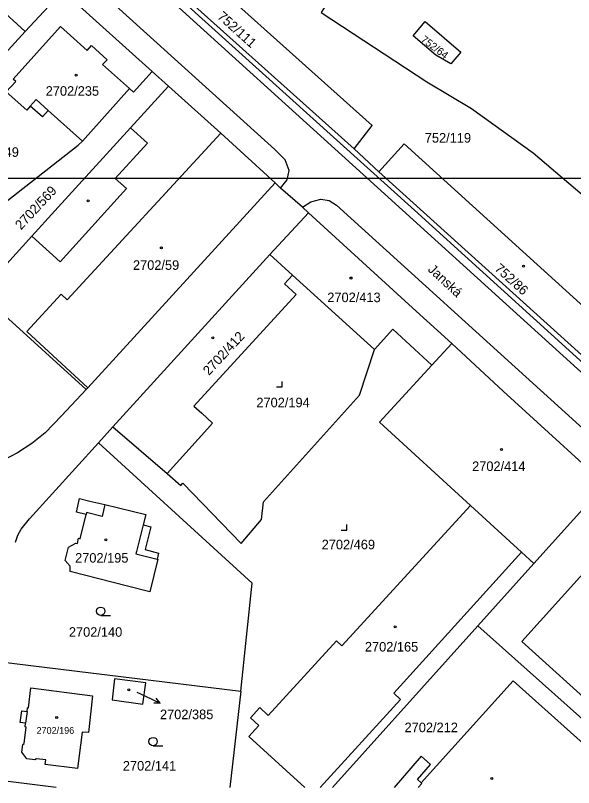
# Model space of a CAD drawing. Extents: x -496682 to -495907, y -1088575 to -1088018.
# Drawn here: x -496295.2 to -496196, y -1088569.4 to -1088432.3 of the extents above; entities that cross this region are included whole.
import ezdxf

# ---------------------------------------------------------------- set-up
doc = ezdxf.new("R2010")
doc.units = 0
for name, color, linetype in [('Hranice parcel', 7, 'Continuous'), ('Parcelní čísla', 7, 'Continuous'), ('Pop  PČ popisy', 7, 'Continuous'), ('Vnitřní kresba', 7, 'Continuous'), ('Vrstva 63', 7, 'Continuous'), ('Značky budov', 7, 'Continuous'), ('Značky kultur', 7, 'Continuous')]:
    doc.layers.add(name, color=color, linetype=linetype)

msp = doc.modelspace()

# ---------------------------------------------------------------- linework, layer by layer
at = {"layer": 'Hranice parcel'}
for p, q in [((-496235.01, -1088455.98), (-496275.42, -1088419.72)), ((-496270.9, -1088442.22), (-496286.81, -1088427.89)), ((-496270.9, -1088442.22), (-496268.01, -1088444.81)), ((-496283.32, -1088454.6), (-496274.93, -1088445.27)), ((-496230.6, -1088460.05), (-496235.01, -1088455.98)), ((-496185.86, -1088500.52), (-496230.6, -1088460.05)), ((-496248.09, -1088462.93), (-496249.03, -1088461.98)), ((-496244.2, -1088466.33), (-496248.09, -1088462.93)), ((-496249.99, -1088474.77), (-496243.12, -1088467.31)), ((-496243.12, -1088467.31), (-496244.2, -1088466.33)), ((-496277.9, -1088505.38), (-496249.99, -1088474.77)), ((-496245.99, -1088478.39), (-496249.99, -1088474.77)), ((-496231.37, -1088491.6), (-496245.99, -1088478.39)), ((-496301.48, -1088481.61), (-496282.64, -1088498.73)), ((-496221.19, -1088494.41), (-496217.64, -1088490.55)), ((-496280.44, -1088508.2), (-496277.9, -1088505.38)), ((-496277.9, -1088505.38), (-496268.24, -1088513.68)), ((-496203.08, -1088529.64), (-496190.39, -1088515.55)), ((-496205.29, -1088527.62), (-496214.35, -1088519.32)), ((-496205.29, -1088527.62), (-496203.08, -1088529.64)), ((-496213.05, -1088540.72), (-496203.08, -1088529.64)), ((-496180.77, -1088569.45), (-496213.05, -1088540.72)), ((-496297.81, -1088547.13), (-496255.13, -1088552.31)), ((-496255.13, -1088552.31), (-496257.1, -1088569.45))]:
    msp.add_line(p, q, dxfattribs=at)
for points in [[(-496248.09, -1088462.93), (-496246.94, -1088461.48), (-496246.55, -1088459.79), (-496247.27, -1088457.92), (-496249.13, -1088456.06), (-496330.94, -1088382.16), (-496352.76, -1088362.17), (-496394.53, -1088322.76)], [(-496113.2, -1088569.45), (-496126.78, -1088557.15), (-496235.31, -1088458.83), (-496335.43, -1088368.13), (-496341.24, -1088361.35)], [(-496263.38, -1088406.35), (-496237.32, -1088426.06), (-496240.89, -1088431.73), (-496222.1, -1088444.04), (-496214.16, -1088448.81), (-496203.17, -1088456.69), (-496183.01, -1088473.86)], [(-496235.01, -1088455.98), (-496231.8, -1088451.84), (-496271.94, -1088415.85)], [(-496111.32, -1088569.45), (-496125.77, -1088556.38), (-496187.85, -1088499.89), (-496224.3, -1088466.84), (-496274.7, -1088421.37), (-496275.92, -1088420.27)], [(-496286.81, -1088427.89), (-496293.46, -1088435.15), (-496314.33, -1088457.95)], [(-496283.32, -1088454.6), (-496289.39, -1088449.15), (-496290.42, -1088450.31), (-496292.57, -1088448.38), (-496293.21, -1088449.09), (-496296.84, -1088445.84), (-496295.16, -1088443.98), (-496295.61, -1088443.57), (-496287.2, -1088434.24), (-496282.48, -1088438.48), (-496281.67, -1088437.59), (-496278.91, -1088440.14), (-496279.72, -1088440.96), (-496274.93, -1088445.27)], [(-496216.02, -1088438.77), (-496217.83, -1088440.84), (-496220.52, -1088439.31), (-496224.52, -1088435.92), (-496222.37, -1088433.36), (-496216.02, -1088438.77)], [(-496274.93, -1088445.27), (-496274.21, -1088445.91), (-496270.9, -1088442.22)], [(-496268.01, -1088444.81), (-496274.79, -1088452.23), (-496288.2, -1088467.01), (-496292.3, -1088471.51), (-496296.73, -1088476.39)], [(-496249.03, -1088461.98), (-496258.73, -1088453.21), (-496268.01, -1088444.81)], [(-496314.33, -1088457.95), (-496301.91, -1088469.21), (-496284.09, -1088455.32), (-496283.32, -1088454.6)], [(-496185.86, -1088500.52), (-496181.41, -1088495.65), (-496226.11, -1088455.1), (-496230.6, -1088460.05)], [(-496282.64, -1088498.73), (-496282.35, -1088498.41), (-496249.03, -1088461.98)], [(-496244.2, -1088466.33), (-496242.71, -1088465.41), (-496240.93, -1088464.91), (-496239.45, -1088465.16), (-496238.15, -1088465.99), (-496132.08, -1088562.07), (-496131.43, -1088562.99), (-496131.42, -1088564), (-496132.07, -1088565.26)], [(-496217.64, -1088490.55), (-496224.63, -1088484.22), (-496243.12, -1088467.31)], [(-496245.99, -1088478.39), (-496247.4, -1088479.95), (-496245.31, -1088481.83), (-496263.51, -1088501.71), (-496262.11, -1088502.91), (-496260.17, -1088504.72), (-496261.08, -1088505.74), (-496268.24, -1088513.68)], [(-496231.37, -1088491.6), (-496228.16, -1088488.03), (-496221.19, -1088494.41)], [(-496190.39, -1088515.55), (-496208.5, -1088499), (-496217.64, -1088490.55)], [(-496268.24, -1088513.68), (-496265.8, -1088515.77), (-496265.43, -1088515.37), (-496255.1, -1088526.07), (-496251.45, -1088521.81), (-496251.15, -1088518.66), (-496234.05, -1088499.76), (-496231.37, -1088491.6)], [(-496221.19, -1088494.41), (-496230.49, -1088504.55), (-496214.35, -1088519.32)], [(-496282.64, -1088498.73), (-496287, -1088503.42), (-496289.92, -1088506.42), (-496292.31, -1088508.31), (-496294.86, -1088509.98), (-496297.59, -1088511.42), (-496300.41, -1088512.61), (-496303.13, -1088513.62), (-496305.98, -1088514.4), (-496309.41, -1088514.94), (-496310.93, -1088514.97), (-496313.55, -1088515.26), (-496317.24, -1088515.06), (-496320.12, -1088514.76), (-496333.4, -1088513.15)], [(-496295.23, -1088525.87), (-496294.76, -1088524.6), (-496294.18, -1088523.56), (-496292.73, -1088521.72), (-496280.44, -1088508.2)], [(-496255.13, -1088552.31), (-496253.14, -1088533.12), (-496280.44, -1088508.2)], [(-496272.18, -1088527.18), (-496269.77, -1088527.8), (-496270.02, -1088528.86), (-496269.9, -1088528.89), (-496271.35, -1088534.65), (-496275.27, -1088533.67), (-496285.51, -1088531.07), (-496285.49, -1088530.11), (-496286.36, -1088529.12), (-496285.77, -1088526.72), (-496284.46, -1088526.04), (-496284.2, -1088526.06), (-496283.99, -1088525.16), (-496283.7, -1088525.23), (-496282.65, -1088520.96), (-496284.33, -1088520.55), (-496283.8, -1088518.12), (-496281.99, -1088518.55), (-496279.33, -1088519.18), (-496272.01, -1088520.93), (-496272.51, -1088522.77), (-496271.14, -1088523.12), (-496272.18, -1088527.18)], [(-496214.35, -1088519.32), (-496237.18, -1088544.25), (-496238.15, -1088543.36), (-496250.3, -1088556.62), (-496251.8, -1088555.25), (-496253.46, -1088557.05), (-496251.95, -1088558.43), (-496253.72, -1088560.35), (-496243.79, -1088569.45)], [(-496170.45, -1088533.31), (-496191.17, -1088556.18), (-496205.21, -1088543.51), (-496184.56, -1088520.66)], [(-496241.07, -1088569.45), (-496226.75, -1088553.82), (-496227.98, -1088552.7), (-496205.29, -1088527.62)], [(-496213.05, -1088540.72), (-496233.07, -1088562.96), (-496238.87, -1088569.45)], [(-496272.06, -1088550.82), (-496277.62, -1088550.13), (-496278.01, -1088553.84), (-496272.54, -1088554.66), (-496272.06, -1088550.82)], [(-496194.13, -1088569.45), (-496190.36, -1088565.18), (-496206.75, -1088550.46), (-496223.07, -1088568.62), (-496223.75, -1088568.03), (-496221.41, -1088565.34), (-496223.08, -1088563.9), (-496227.89, -1088569.45)], [(-496291.47, -1088564.36), (-496291.75, -1088564.53), (-496293.19, -1088564.36), (-496294.05, -1088563.16), (-496293.88, -1088561.8), (-496293.68, -1088561.61), (-496293.33, -1088558.7), (-496293.49, -1088558.66), (-496293.41, -1088558.01), (-496294.37, -1088557.89), (-496294.09, -1088555.81), (-496293.15, -1088555.93), (-496293.06, -1088555.28), (-496292.91, -1088555.28), (-496292.48, -1088551.75), (-496281.49, -1088553.16), (-496282.22, -1088559.69), (-496283.33, -1088559.6), (-496284.17, -1088566.05), (-496289.9, -1088565.34)], [(-496289.9, -1088565.34), (-496289.8, -1088564.54), (-496291.47, -1088564.36)], [(-496287.95, -1088569.45), (-496300.36, -1088567.89)]]:
    msp.add_lwpolyline(points, dxfattribs=at)
at = {"layer": 'Pop  PČ popisy'}
for p, q in [((-496273.63, -1088552.52), (-496272.23, -1088553.18)), ((-496272.23, -1088553.18), (-496269.51, -1088554.45)), ((-496269.51, -1088554.45), (-496270.21, -1088553.57)), ((-496269.51, -1088554.45), (-496270.63, -1088554.48))]:
    msp.add_line(p, q, dxfattribs=at)
at = {"layer": 'Vnitřní kresba'}
for p, q in [((-496293.46, -1088435.15), (-496311.39, -1088418.91)), ((-496291.53, -1088447.22), (-496292.57, -1088448.38)), ((-496289.39, -1088449.15), (-496291.53, -1088447.22)), ((-496271.73, -1088454.95), (-496274.79, -1088452.23)), ((-496285.99, -1088482.77), (-496258.73, -1088453.21)), ((-496277.51, -1088461.21), (-496271.73, -1088454.95)), ((-496275.48, -1088463.04), (-496277.51, -1088461.21)), ((-496287.29, -1088476.05), (-496275.48, -1088463.04)), ((-496292.3, -1088471.51), (-496287.29, -1088476.05)), ((-496293.16, -1088488.43), (-496287.06, -1088481.79)), ((-496287.06, -1088481.79), (-496285.99, -1088482.77)), ((-496282.35, -1088498.41), (-496293.16, -1088488.43)), ((-496279.33, -1088519.18), (-496279.82, -1088521.27)), ((-496282.56, -1088520.59), (-496282.65, -1088520.96)), ((-496279.82, -1088521.27), (-496282.56, -1088520.59)), ((-496272.51, -1088522.77), (-496273.69, -1088527.5)), ((-496273.69, -1088527.5), (-496273.8, -1088527.93)), ((-496273.8, -1088527.93), (-496270.02, -1088528.86)), ((-496293.15, -1088555.93), (-496293.41, -1088558.01)), ((-496222.98, -1088568.7), (-496223.63, -1088569.45)), ((-496223.07, -1088568.62), (-496222.98, -1088568.7))]:
    msp.add_line(p, q, dxfattribs=at)
at = {"layer": 'Vrstva 63'}
msp.add_lwpolyline([(-496137.35, -1088164.24), (-496137.35, -1088461.24), (-496557.35, -1088461.24), (-496557.35, -1088164.24)], close=True, dxfattribs=at)
at = {"layer": 'Značky budov'}
for centre in [(-496284.4, -1088442.87), (-496282.3, -1088465.22), (-496269.28, -1088473.54), (-496204.92, -1088476.81), (-496235.57, -1088478.92), (-496260.15, -1088489.55), (-496208.84, -1088509.38), (-496279.16, -1088525.43), (-496227.72, -1088540.88), (-496275.05, -1088552.07), (-496287.88, -1088556.98), (-496210.55, -1088567.84)]:
    msp.add_circle(centre, 0.175, dxfattribs=at)
at = {"layer": 'Značky kultur'}
for p, q in [((-496247.79, -1088498.28), (-496247.79, -1088497.28)), ((-496248.79, -1088498.28), (-496247.79, -1088498.28)), ((-496236.29, -1088523.7), (-496236.29, -1088522.7)), ((-496237.29, -1088523.7), (-496236.29, -1088523.7)), ((-496280.06, -1088538.88), (-496278.31, -1088538.88)), ((-496270.75, -1088562.03), (-496269, -1088562.03))]:
    msp.add_line(p, q, dxfattribs=at)
for centre in [(-496280.06, -1088538.13), (-496270.75, -1088561.28)]:
    msp.add_circle(centre, 0.75, dxfattribs=at)

# ---------------------------------------------------------------- texts
at = {"layer": 'Parcelní čísla'}
for s, height, rotation, p in [('752/111', 1.7, 318, (-496259.43, -1088432.66)), ('752/64', 1.334, 323, (-496223.27, -1088436.8)), ('2702/569', 1.7, 47, (-496294.21, -1088470.46)), ('752/86', 1.7, 318, (-496210.18, -1088477.44)), ('2702/412', 1.7, 47, (-496260.82, -1088496.33))]:
    msp.add_text(s, height=height, rotation=rotation, dxfattribs=at).set_placement(p)
for s, height, p in [('2702/235', 1.7, (-496289.83, -1088446.54)), ('752/119', 1.7, (-496222.45, -1088454.86)), ('2702/149', 1.7, (-496304.08, -1088457.39)), ('2702/59', 1.7, (-496274.32, -1088477.47)), ('2702/413', 1.7, (-496239.78, -1088483.21)), ('2702/194', 1.7, (-496252.39, -1088501.89)), ('2702/414', 1.7, (-496214.04, -1088513.21)), ('2702/469', 1.7, (-496240.78, -1088527.12)), ('2702/195', 1.7, (-496284.61, -1088529.49)), ('2702/140', 1.7, (-496285.71, -1088542.66)), ('2702/165', 1.7, (-496233.1, -1088545.28)), ('2702/385', 1.7, (-496269.52, -1088557.3)), ('2702/212', 1.7, (-496226.05, -1088559.61)), ('2702/196', 1.2, (-496291.46, -1088559.9)), ('2702/141', 1.7, (-496276.12, -1088566.43))]:
    msp.add_text(s, height=height, dxfattribs=at).set_placement(p)
at = {"layer": 'Pop  PČ popisy'}
msp.add_text('Janská', height=1.7, rotation=317, dxfattribs=at).set_placement((-496222.03, -1088477.54))

doc.saveas('drawing.dxf')
